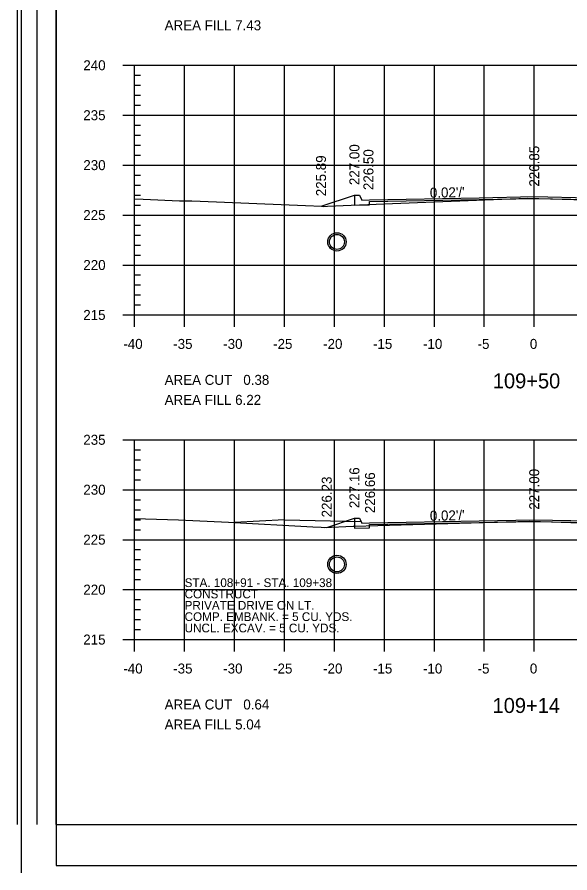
# Model space of a CAD drawing. Extents: x 1367903 to 1373764, y 376865 to 382130.
# Drawn here: x 1372116.6 to 1372227.3, y 377279.1 to 377450.5 of the extents above; entities that cross this region are included whole.
import ezdxf

# ---------------------------------------------------------------- set-up
doc = ezdxf.new("R2010")
doc.units = 0
for name, color, linetype in [('R_Axis', 7, 'Continuous'), ('R_Axis Annot', 7, 'Continuous'), ('R_Border', 7, 'Continuous'), ('R_Border PE', 7, 'Continuous'), ('R_Draft', 7, 'Continuous'), ('R_Drive', 7, 'Continuous'), ('R_Exist Surface', 7, 'Continuous'), ('R_Fin Surface', 7, 'Continuous'), ('R_Fin Surface Annot', 7, 'Continuous'), ('R_Grid', 7, 'Continuous'), ('R_Water', 7, 'Continuous')]:
    doc.layers.add(name, color=color, linetype=linetype)

msp = doc.modelspace()

# ---------------------------------------------------------------- linework, layer by layer
for points in [[(1372184.16, 377414.84), (1372184.16, 377414.17), (1372184.16, 377414.17), (1372184.16, 377412.81), (1372187.16, 377412.87), (1372187.16, 377413.53), (1372220.16, 377414.19), (1372253.16, 377413.53), (1372253.16, 377412.87), (1372256.16, 377412.81), (1372256.16, 377414.25), (1372270.16, 377414.53), (1372270.16, 377415.12)], [(1372184.16, 377350.15), (1372184.16, 377349.48), (1372184.16, 377349.48), (1372184.16, 377348.12), (1372187.16, 377348.18), (1372187.16, 377348.85), (1372220.16, 377349.51), (1372253.16, 377348.85), (1372253.16, 377348.18), (1372256.16, 377348.12), (1372256.16, 377349.56), (1372270.16, 377349.84), (1372270.16, 377350.43)]]:
    msp.add_lwpolyline(points)
at = {"layer": 'R_Axis'}
for p, q in [((1372137.76, 377440.84), (1372142.56, 377440.84)), ((1372140.16, 377390.84), (1372140.16, 377440.84)), ((1372140.16, 377438.84), (1372141.36, 377438.84)), ((1372140.16, 377436.84), (1372141.36, 377436.84)), ((1372140.16, 377434.84), (1372141.36, 377434.84)), ((1372140.16, 377432.84), (1372141.36, 377432.84)), ((1372137.76, 377430.84), (1372142.56, 377430.84)), ((1372140.16, 377428.84), (1372141.36, 377428.84)), ((1372140.16, 377426.84), (1372141.36, 377426.84)), ((1372140.16, 377424.84), (1372141.36, 377424.84)), ((1372140.16, 377422.84), (1372141.36, 377422.84)), ((1372137.76, 377420.84), (1372142.56, 377420.84)), ((1372140.16, 377418.84), (1372141.36, 377418.84)), ((1372140.16, 377416.84), (1372141.36, 377416.84)), ((1372140.16, 377414.84), (1372141.36, 377414.84)), ((1372140.16, 377412.84), (1372141.36, 377412.84)), ((1372137.76, 377410.84), (1372142.56, 377410.84)), ((1372140.16, 377408.84), (1372141.36, 377408.84)), ((1372140.16, 377406.84), (1372141.36, 377406.84)), ((1372140.16, 377404.84), (1372141.36, 377404.84)), ((1372140.16, 377402.84), (1372141.36, 377402.84)), ((1372137.76, 377400.84), (1372142.56, 377400.84)), ((1372140.16, 377398.84), (1372141.36, 377398.84)), ((1372140.16, 377396.84), (1372141.36, 377396.84)), ((1372140.16, 377394.84), (1372141.36, 377394.84)), ((1372140.16, 377388.44), (1372140.16, 377393.24)), ((1372150.16, 377388.44), (1372150.16, 377393.24)), ((1372160.16, 377388.44), (1372160.16, 377393.24)), ((1372170.16, 377388.44), (1372170.16, 377393.24)), ((1372180.16, 377388.44), (1372180.16, 377393.24)), ((1372190.16, 377388.44), (1372190.16, 377393.24)), ((1372200.16, 377388.44), (1372200.16, 377393.24)), ((1372210.16, 377388.44), (1372210.16, 377393.24)), ((1372220.16, 377388.44), (1372220.16, 377393.24)), ((1372140.16, 377392.84), (1372141.36, 377392.84)), ((1372137.76, 377390.84), (1372142.56, 377390.84)), ((1372140.16, 377390.84), (1372300.16, 377390.84)), ((1372137.76, 377365.84), (1372142.56, 377365.84)), ((1372140.16, 377325.84), (1372140.16, 377365.84)), ((1372140.16, 377363.84), (1372141.36, 377363.84)), ((1372140.16, 377361.84), (1372141.36, 377361.84)), ((1372140.16, 377359.84), (1372141.36, 377359.84)), ((1372140.16, 377357.84), (1372141.36, 377357.84)), ((1372137.76, 377355.84), (1372142.56, 377355.84)), ((1372140.16, 377353.84), (1372141.36, 377353.84)), ((1372140.16, 377351.84), (1372141.36, 377351.84)), ((1372140.16, 377349.84), (1372141.36, 377349.84)), ((1372140.16, 377347.84), (1372141.36, 377347.84)), ((1372137.76, 377345.84), (1372142.56, 377345.84)), ((1372140.16, 377343.84), (1372141.36, 377343.84)), ((1372140.16, 377341.84), (1372141.36, 377341.84)), ((1372140.16, 377339.84), (1372141.36, 377339.84)), ((1372140.16, 377337.84), (1372141.36, 377337.84)), ((1372137.76, 377335.84), (1372142.56, 377335.84)), ((1372140.16, 377333.84), (1372141.36, 377333.84)), ((1372140.16, 377331.84), (1372141.36, 377331.84)), ((1372140.16, 377329.84), (1372141.36, 377329.84)), ((1372140.16, 377323.44), (1372140.16, 377328.24)), ((1372140.16, 377327.84), (1372141.36, 377327.84)), ((1372150.16, 377323.44), (1372150.16, 377328.24)), ((1372160.16, 377323.44), (1372160.16, 377328.24)), ((1372170.16, 377323.44), (1372170.16, 377328.24)), ((1372180.16, 377323.44), (1372180.16, 377328.24)), ((1372190.16, 377323.44), (1372190.16, 377328.24)), ((1372200.16, 377323.44), (1372200.16, 377328.24)), ((1372210.16, 377323.44), (1372210.16, 377328.24)), ((1372220.16, 377323.44), (1372220.16, 377328.24)), ((1372137.76, 377325.84), (1372142.56, 377325.84)), ((1372140.16, 377325.84), (1372300.16, 377325.84))]:
    msp.add_line(p, q, dxfattribs=at)
at = {"layer": 'R_Border'}
for p, q in [((1372117.43, 377620.35), (1372117.43, 377279.12)), ((1372124.46, 377611.47), (1372124.46, 377280.59)), ((1372124.46, 377280.59), (1372328.78, 377280.59))]:
    msp.add_line(p, q, dxfattribs=at)
at = {"layer": 'R_Border PE'}
for p, q in [((1372116.63, 377610.76), (1372116.63, 377288.8)), ((1372120.54, 377610.76), (1372120.54, 377288.8)), ((1372124.46, 377288.8), (1372124.46, 377603.25)), ((1372124.46, 377288.8), (1372328.78, 377288.8))]:
    msp.add_line(p, q, dxfattribs=at)
at = {"layer": 'R_Drive'}
for q in [(1372160.16, 377349.25), (1372185.49, 377349.49)]:
    msp.add_line((1372170.16, 377349.79), q, dxfattribs=at)
at = {"layer": 'R_Exist Surface'}
for points in [[(1372140.16, 377414.11), (1372141.89, 377414.01), (1372149.15, 377413.67), (1372151.58, 377413.68), (1372153.27, 377413.6), (1372174.37, 377412.73), (1372177.62, 377412.6), (1372177.9, 377412.56), (1372178.77, 377412.65), (1372183.5, 377412.85), (1372196.78, 377413.39), (1372218.75, 377414.24), (1372246.71, 377413.4), (1372255.48, 377413.12), (1372257.57, 377413.44), (1372258.98, 377413.56), (1372262.27, 377413.95), (1372264.5, 377414.21), (1372270.2, 377414.55), (1372273.34, 377414.75), (1372277.83, 377415.11), (1372286.66, 377415.67), (1372292.07, 377415.84), (1372300.16, 377416.2)], [(1372140.16, 377350.1), (1372148.93, 377349.8), (1372151.81, 377349.69), (1372158.92, 377349.32), (1372175.81, 377348.39), (1372177.49, 377348.34), (1372178.1, 377348.28), (1372183.88, 377348.54), (1372184.1, 377348.55), (1372188.86, 377348.68), (1372219.2, 377349.55), (1372223.62, 377349.41), (1372254.47, 377348.35), (1372256.06, 377348.64), (1372257.7, 377348.74), (1372260.36, 377349.07), (1372261.23, 377349.25), (1372262.07, 377349.33), (1372270.86, 377349.82), (1372273.99, 377350.12), (1372285.57, 377351.43), (1372294.15, 377351.55), (1372300.16, 377351.64)]]:
    msp.add_lwpolyline(points, dxfattribs=at)
at = {"layer": 'R_Fin Surface'}
for points in [[(1372177.47, 377412.61), (1372184.16, 377414.84), (1372185.16, 377414.84), (1372185.66, 377413.84), (1372187.16, 377413.87), (1372209.16, 377414.31), (1372220.16, 377414.53), (1372231.16, 377414.31), (1372253.16, 377413.87), (1372254.66, 377413.84), (1372255.16, 377414.84), (1372256.16, 377414.84), (1372260.16, 377414.92), (1372270.16, 377415.12), (1372271.59, 377414.64)], [(1372178.62, 377348.3), (1372184.16, 377350.15), (1372185.16, 377350.15), (1372185.66, 377349.15), (1372187.16, 377349.18), (1372209.16, 377349.62), (1372220.16, 377349.84), (1372231.16, 377349.62), (1372253.16, 377349.18), (1372254.66, 377349.15), (1372255.16, 377350.15), (1372256.16, 377350.15), (1372260.16, 377350.23), (1372270.16, 377350.43), (1372271.74, 377349.9)]]:
    msp.add_lwpolyline(points, dxfattribs=at)
at = {"layer": 'R_Grid'}
for p, q in [((1372140.16, 377440.84), (1372300.16, 377440.84)), ((1372140.16, 377390.84), (1372140.16, 377440.84)), ((1372150.16, 377390.84), (1372150.16, 377440.84)), ((1372160.16, 377390.84), (1372160.16, 377440.84)), ((1372170.16, 377390.84), (1372170.16, 377440.84)), ((1372180.16, 377390.84), (1372180.16, 377440.84)), ((1372190.16, 377390.84), (1372190.16, 377440.84)), ((1372200.16, 377390.84), (1372200.16, 377440.84)), ((1372210.16, 377390.84), (1372210.16, 377440.84)), ((1372220.16, 377390.84), (1372220.16, 377440.84)), ((1372140.16, 377430.84), (1372300.16, 377430.84)), ((1372140.16, 377420.84), (1372300.16, 377420.84)), ((1372140.16, 377410.84), (1372300.16, 377410.84)), ((1372140.16, 377400.84), (1372300.16, 377400.84)), ((1372140.16, 377390.84), (1372300.16, 377390.84)), ((1372140.16, 377365.84), (1372300.16, 377365.84)), ((1372140.16, 377325.84), (1372140.16, 377365.84)), ((1372150.16, 377325.84), (1372150.16, 377365.84)), ((1372160.16, 377325.84), (1372160.16, 377365.84)), ((1372170.16, 377325.84), (1372170.16, 377365.84)), ((1372180.16, 377325.84), (1372180.16, 377365.84)), ((1372190.16, 377325.84), (1372190.16, 377365.84)), ((1372200.16, 377325.84), (1372200.16, 377365.84)), ((1372210.16, 377325.84), (1372210.16, 377365.84)), ((1372220.16, 377325.84), (1372220.16, 377365.84)), ((1372140.16, 377355.84), (1372300.16, 377355.84)), ((1372140.16, 377345.84), (1372300.16, 377345.84)), ((1372140.16, 377335.84), (1372300.16, 377335.84)), ((1372140.16, 377325.84), (1372300.16, 377325.84))]:
    msp.add_line(p, q, dxfattribs=at)
at = {"layer": 'R_Water'}
for p, q in [((1372180.66, 377407.33), (1372180.66, 377407.28)), ((1372180.66, 377406.99), (1372180.66, 377406.94)), ((1372180.66, 377403.99), (1372180.66, 377403.94)), ((1372180.66, 377403.66), (1372180.66, 377403.61)), ((1372180.66, 377342.75), (1372180.66, 377342.7)), ((1372180.66, 377342.42), (1372180.66, 377342.37)), ((1372180.66, 377339.42), (1372180.66, 377339.37)), ((1372180.66, 377339.09), (1372180.66, 377339.04))]:
    msp.add_line(p, q, dxfattribs=at)
for centre, radius in [((1372180.66, 377405.47), 1.83), ((1372180.66, 377405.47), 1.5), ((1372180.66, 377340.9), 1.83), ((1372180.66, 377340.9), 1.5)]:
    msp.add_circle(centre, radius, dxfattribs=at)

# ---------------------------------------------------------------- texts
at = {"layer": 'R_Axis Annot'}
for s, height, p in [('AREA FILL 7.43', 2, (1372146.16, 377447.84)), ('240', 2, (1372129.88, 377439.84)), ('235', 2, (1372129.87, 377429.84)), ('230', 2, (1372129.88, 377419.84)), ('225', 2, (1372129.87, 377409.84)), ('220', 2, (1372129.88, 377399.84)), ('215', 2, (1372129.87, 377389.84)), ('-40', 2, (1372137.89, 377384.04)), ('-35', 2, (1372147.88, 377384.04)), ('-30', 2, (1372157.89, 377384.04)), ('-25', 2, (1372167.88, 377384.04)), ('-20', 2, (1372177.89, 377384.04)), ('-15', 2, (1372187.88, 377384.04)), ('-10', 2, (1372197.89, 377384.04)), ('-5', 2, (1372208.82, 377384.04)), ('0', 2, (1372219.28, 377384.04)), ('AREA CUT   0.38', 2, (1372146.16, 377376.84)), ('109+50', 3, (1372211.87, 377376.14)), ('AREA FILL 6.22', 2, (1372146.16, 377372.84)), ('235', 2, (1372129.87, 377364.84)), ('230', 2, (1372129.88, 377354.84)), ('225', 2, (1372129.87, 377344.84)), ('220', 2, (1372129.88, 377334.84)), ('215', 2, (1372129.87, 377324.84)), ('-40', 2, (1372137.89, 377319.04)), ('-35', 2, (1372147.88, 377319.04)), ('-30', 2, (1372157.89, 377319.04)), ('-25', 2, (1372167.88, 377319.04)), ('-20', 2, (1372177.89, 377319.04)), ('-15', 2, (1372187.88, 377319.04)), ('-10', 2, (1372197.89, 377319.04)), ('-5', 2, (1372208.82, 377319.04)), ('0', 2, (1372219.28, 377319.04)), ('109+14', 3, (1372211.82, 377311.14)), ('AREA CUT   0.64', 2, (1372146.16, 377311.84)), ('AREA FILL 5.04', 2, (1372146.16, 377307.84))]:
    msp.add_text(s, height=height, dxfattribs=at).set_placement(p)
at = {"layer": 'R_Draft'}
for s, p in [('STA. 108+91 - STA. 109+38', (1372150.16, 377336.35)), ('CONSTRUCT', (1372150.16, 377334.09)), ('PRIVATE DRIVE ON LT.', (1372150.16, 377331.82)), ('COMP. EMBANK. = 5 CU. YDS.', (1372150.16, 377329.55)), ('UNCL. EXCAV. = 5 CU. YDS.', (1372150.16, 377327.28))]:
    msp.add_text(s, height=1.75, dxfattribs=at).set_placement(p)
at = {"layer": 'R_Fin Surface Annot'}
for s, rotation, p in [('227.00', 90, (1372185.16, 377416.84)), ('226.50', 90, (1372187.97, 377415.84)), ('226.85', 90, (1372221.16, 377416.53)), ('225.89', 90, (1372178.47, 377414.61)), ("0.02'/'", 1.1458, (1372199.28, 377414.31)), ('227.16', 90, (1372185.16, 377352.15)), ('226.66', 90, (1372188.28, 377351.15)), ('227.00', 90, (1372221.16, 377351.84)), ('226.23', 90, (1372179.62, 377350.3)), ("0.02'/'", 1.1458, (1372199.28, 377349.62))]:
    msp.add_text(s, height=2, rotation=rotation, dxfattribs=at).set_placement(p)

doc.saveas('drawing.dxf')
